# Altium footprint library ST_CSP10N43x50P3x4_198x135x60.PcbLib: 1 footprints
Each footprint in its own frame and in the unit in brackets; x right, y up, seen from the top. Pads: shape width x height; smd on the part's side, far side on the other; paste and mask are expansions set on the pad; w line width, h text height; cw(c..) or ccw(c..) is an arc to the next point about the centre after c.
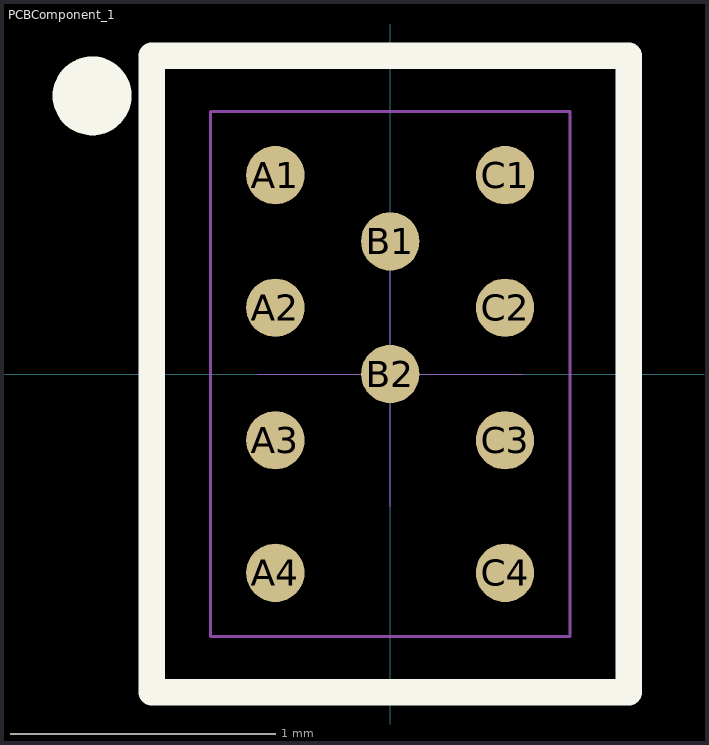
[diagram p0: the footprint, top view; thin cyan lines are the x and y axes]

## PCBComponent_1 [mm]
pads (10):
  round 0.22 smd paste-20 mask+0.04: A1(-0.433,0.75) A2(-0.433,0.25) A3(-0.433,-0.25) A4(-0.433,-0.75) B1(0,0.5) B2(0,0) C1(0.433,0.75) C2(0.433,0.25) C3(0.433,-0.25) C4(0.433,-0.75)
Top Overlay:
  circle w0.2: c-1.124,1.049 r0.049
  lines w0.1: -0.9,-1.2 -0.9,1.2 0.9,1.2 0.9,-1.2 -0.9,-1.2
Top Paste:
  rectangle: 0.323,-0.86 0.543,-0.64
  rectangle: -0.543,-0.86 -0.323,-0.64
  rectangle: 0.323,-0.36 0.543,-0.14
  rectangle: -0.543,-0.36 -0.323,-0.14
  rectangle: 0.323,0.14 0.543,0.36
  rectangle: -0.11,-0.11 0.11,0.11
  rectangle: -0.543,0.14 -0.323,0.36
  rectangle: -0.11,0.39 0.11,0.61
  rectangle: 0.323,0.64 0.543,0.86
  rectangle: -0.543,0.64 -0.323,0.86
Mechanical 15:
  lines w0.001: -0.5,0 0.5,0 ; 0,-0.5 0,0.5
  lines w0.01: -0.678,-0.99 -0.678,0.99 0.678,0.99 0.678,-0.99 -0.678,-0.99
3D body: height 0.66, standoff 0.25, extent -0.678,-0.99 0.678,0.99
